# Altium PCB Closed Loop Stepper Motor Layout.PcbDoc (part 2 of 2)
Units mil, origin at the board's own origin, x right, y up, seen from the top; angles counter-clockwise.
Board outline 3560 x 2030 mil, 2 copper layers (Top Layer, Bottom Layer), stack 64.8 mil thick; 66 components, 54 nets, 285 pads, 203 vias.
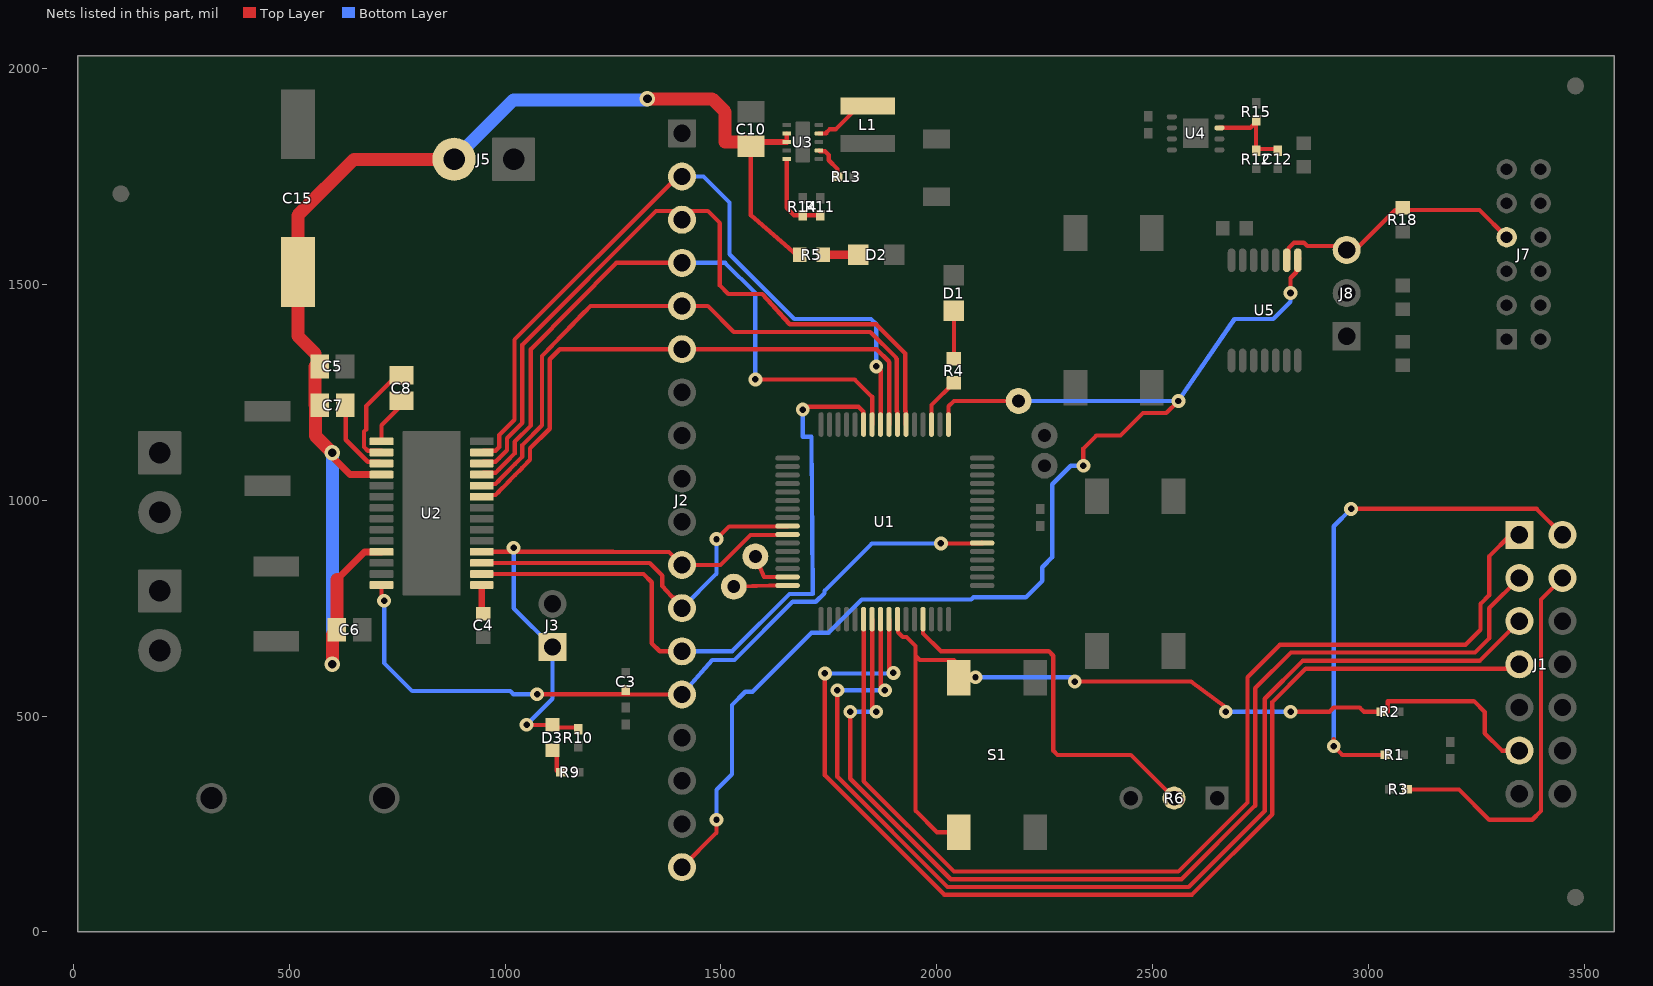
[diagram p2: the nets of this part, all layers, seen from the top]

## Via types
v1: diameter 32, hole 15, Top Layer to Bottom Layer, 165 vias
v2: diameter 19.68, hole 7.87, Top Layer to Bottom Layer, 16 vias
v3: diameter 19.68, hole 7.87, Top Layer to Bottom Layer, tented both sides, 12 vias
v4: diameter 36, hole 20, Top Layer to Bottom Layer, 4 vias
v5: diameter 32, hole 16, Top Layer to Bottom Layer, 3 vias
v6: diameter 32/32 (per signal layer), hole 16, Top Layer to Bottom Layer, 2 vias
v7: diameter 50, hole 28, Top Layer to Bottom Layer, 1 vias

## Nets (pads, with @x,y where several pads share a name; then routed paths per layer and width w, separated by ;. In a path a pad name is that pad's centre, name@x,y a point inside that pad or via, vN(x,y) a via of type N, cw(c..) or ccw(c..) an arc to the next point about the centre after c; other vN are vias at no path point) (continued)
I_ENCODER_3.3V: J2.18 pad.13 U1.17 U5.8 | length 2955.8
  Top Layer w10: J2.18@1410,150 1490,230 v1(1490,260) ; U1.17@2027.64,1175.39 2027.64,1217.64 2040,1230 pad.13@2190,1230 ; v1(2340,1080) 2340,1120 2370,1150 2425.9,1150 2477.95,1202.05 2532.05,1202.05 v1(2560,1230) ; v5(2820,1480) 2820,1515.71 2820.18,1515.71 2832.91,1528.44 2832.91,1552.28 U5.8@2840.63,1560
  Bottom Layer w10: v1(1490,260) 1490,329.37 1525.75,365.12 1525.75,525.75 1556.38,556.38 1573.33,556.38 1710.26,693.31 1749.7,693.31 1826.39,770 2080,770 2085.38,775.38 2206.77,775.38 2244.62,813.23 2244.62,845.01 2267.87,868.27 2267.87,1037.13 2310.75,1080 v1(2340,1080) ; pad.13@2190,1230 v1(2560,1230) 2690,1420 2780,1420 2820,1460 v5(2820,1480)
IENC_5V: J7.7 J8.3 R18.1 U5.9 | length 611.1
  Top Layer w10: U5.9@2815.04,1560 2815.04,1583.84 2827.77,1596.57 2850.8,1596.57 2858.5,1588.87 J8.3@2978.87,1588.87 ; J8.3@2970,1580 J8.3@2978.87,1588.87 ; J7.7@3320.63,1609.37 3257.64,1672.36 3080,1672.36 3062.36,1672.36 J8.3@2978.87,1588.87
M0: J2.4 U1.26 U2.25 | length 1537.8
  Top Layer w10: U2.25@946.14,1059.57 950,1063.43 977.89,1063.43 986.57,1072.11 986.57,1072.42 1004.45,1090.3 1004.45,1090.61 1022.32,1108.48 1022.32,1135.75 1060,1173.43 1060,1350 1257.87,1550 J2.4@1410,1550 ; v1(1580,1280) 1810,1280 1850.47,1239.53 U1.26@1850.47,1175.39
  Bottom Layer w10: J2.4@1410,1550 1510,1550 1580,1480 v1(1580,1280)
M1: J2.5 U1.23 U2.24 | length 1429.5
  Top Layer w10: U2.24@946.14,1033.98 950,1037.83 977.89,1037.83 986.57,1046.52 986.57,1046.83 1004.45,1064.7 1004.45,1065.02 1022.32,1082.89 1022.32,1083.2 1040.2,1101.08 1040.2,1128.03 1085.75,1173.58 1085.75,1334.34 1185,1436.76 1198.25,1450 J2.5@1390,1450 ; J2.5@1410,1450 1470,1450 1530,1390 1846.11,1390 1906.75,1329.36 1906.75,1328.53 1907.87,1327.4 1907.87,1206.56 1908.62,1205.81 1908.62,1176.3 U1.23@1909.53,1175.39
MSP_RST: J1.11 R2.1 S1.3 S1.4 U1.58 | length 2150.4
  Top Layer w10: U1.58@1909.53,724.61 1910.43,723.7 1910.43,694.19 1921.43,683.19 1930,683.19 1950.94,662.24 1950.94,640 ; S1.4@2051.42,230.87 2001.02,230.87 1950.94,280.94 1950.94,640 ; v1(2090,590) 2080,590 2040,630 1960.94,630 1950.94,640 ; v1(2320,580) 2590,580 2670,520 v1(2670,510) ; v1(2820,510) 2910,510 2920,520 2980,520 2990,510 3026.38,510 3045,510 3045,534.68 3244.68,534.68 3270,509.37 3270,460 3310,420 J1.11@3350,420
  Bottom Layer w10: v1(2090,590) 2310,590 v1(2320,580) ; v1(2670,510) v1(2820,510)
NetC8_1: C8.1 U2.2 | length 260.5
  Top Layer w10: U2.2@713.86,1110.75 713.86,1114.61 682.11,1114.61 673.43,1123.29 673.43,1159.14 678.35,1164.06 678.35,1218.35 C8.1@760,1300
NetC8_2: C8.2 U2.1 | length 105.3
  Top Layer w10: U2.1@716.34,1136.34 U2.1@713.86,1136.34 713.86,1173.86 C8.2@760,1220
NetC12_2: C12.2 R12.1 R15.2 U4.3 | length 203.3
  Top Layer w10: U4.3@2655.12,1862.8 2726.42,1862.8 2740,1876.38 2740,1813.62 C12.2@2790,1813.62
NetD1_1: D1.1 R4.1 | length 107.2
  Top Layer w10: R4.1@2040,1331.5 D1.1@2040,1438.66
NetD2_1: D2.1 R5.1 | length 77.2
  Top Layer w20: R5.1@1741.5,1568.7 D2.1@1818.66,1568.7
NetD3_1: D3.1 R9.1 | length 47.2
  Top Layer w10: R9.1@1120,373.31 D3.1@1120,420.47
NetJ1_2: J1.2 R1.1 | length 1222.5
  Top Layer w10: 2920,446.38 v1(2920,430) 2940,410 R1.1@3036.38,410 ; v1(2960,980) 3390,980 J1.2@3450,920
  Bottom Layer w10: v1(2920,430) 2920,940 v1(2960,980)
NetJ1_4: J1.4 R3.1 | length 904.4
  Top Layer w10: R3.1@3093.62,330 3210,330 3280,260 3380,260 3400,280 3400,770 J1.4@3450,820
NetL1_1: L1.1 U3.9 | length 120.1
  Top Layer w10: U3.9@1727.4,1849.69 1744.13,1849.69 1744.13,1851.71 1751.68,1859.25 1765.94,1859.25 L1.1@1820,1913.31
NetR11_1: R11.1 R14.1 U3.5 | length 197.7
  Top Layer w10: U3.5@1652.6,1790.63 1652.6,1677.4 1669.69,1660.31 R14.1@1690,1660.31 R11.1@1730,1660.31
NetR13_1: R13.1 U3.7 | length 85.2
  Top Layer w10: U3.7@1727.4,1810.32 1729.29,1808.43 1741.42,1808.43 1750.12,1799.73 1750.12,1787.6 1770.32,1767.4 R13.1@1770.32,1750
NFAULT: D3.2 J2.11 J3.1 R10.1 U1.42 U2.18 | length 1369.4
  Top Layer w10: U2.18@946.14,880.43 1250,880.43 1380,880 J2.11@1410,850 J2.11@1430,850 ; v1(1050,480) 1050.47,479.53 D3.2@1110,479.53 D3.2@1115.91,479.53 ; D3.2@1115.91,473.62 R10.1@1170,473.62 ; J2.11@1410,870 J2.11@1430,850 ; U1.42@1653.7,919.57 1568.93,919.57 1499.37,850 J2.11@1430,850
  Bottom Layer w10: v1(1020,890) 1020,750 J3.1@1110,660 1110,540 v1(1050,480)
NSLEEP: J2.12 U1.41 U2.17 | length 941.3
  Top Layer w10: U2.17@946.14,854.84 1335.16,854.84 1364.65,825.35 1364.65,801.21 J2.12@1410,750 ; J2.12@1391.21,774.65 1408.36,774.65 J2.12@1410,773.01 ; J2.12@1410,770 J2.12@1430,750 ; v1(1490,910) 1519.25,939.25 1653.7,939.25 U1.41@1654.61,940.16
  Bottom Layer w10: J2.12@1410,750 1490,830 v1(1490,910)
P1.6: pad.5 U1.47 | length 106.6
  Top Layer w10: pad.5@1580,870 1600,822.05 U1.47@1654.61,822.05
P1.7: pad.6 U1.48 | length 124.6
  Top Layer w10: pad.6@1530,800 1612.36,802.36 U1.48@1654.61,802.36
POT: R6.2 U1.61 | length 901.5
  Top Layer w10: U1.61@1968.58,724.61 1968.58,691.42 2010,650 2260,650 2270,640 2270,420 2280,410 2450,410 R6.2@2550,310
STATUS: R4.2 U1.19 | length 119.8
  Top Layer w10: U1.19@1989.17,1176.3 U1.19@1988.27,1175.39 1988.27,1220.71 R4.2@2040,1272.44
STEP: J2.6 U1.24 U2.23 | length 1367.7
  Top Layer w10: U2.23@946.14,1008.39 950,1012.24 977.89,1012.24 986.57,1020.93 986.57,1021.24 1004.45,1039.11 1004.45,1039.43 1022.32,1057.3 1022.32,1057.61 1040.2,1075.49 1040.2,1075.8 1058.07,1093.67 1058.07,1120.31 1103.62,1165.87 1103.62,1326.83 1126.8,1350 J2.6@1410,1350 ; J2.6@1400,1360 J2.6@1410,1350 ; U1.24@1889.84,1175.39 1890,1175.55 1890,1320 1888.87,1321.13 1888.87,1321.96 1860.83,1350 J2.6@1410,1350
TCK: J1.7 U1.57 | length 2620.8
  Top Layer w10: v1(1741.13,598.87) 1741.13,363.04 2017.79,86.38 2591.66,86.38 2777.87,272.6 2777.87,532.6 2855.28,610 3340,610 J1.7@3350,620 ; U1.57@1889.84,724.61 1889.84,610.16 v1(1900,600)
  Bottom Layer w10: v1(1741.13,598.87) 1898.87,598.87 v1(1900,600)
TDI: J1.3 U1.55 | length 2569.5
  Top Layer w10: v1(1800,510) 1800,354.72 2032.6,122.13 2567.4,122.13 2737.87,292.6 2737.87,564.39 2820.75,647.26 3247.26,647.26 3280,680 3280,750 J1.3@3350,820 ; U1.55@1850.47,724.61 1850.47,519.53 v1(1860,510)
  Bottom Layer w10: v1(1800,510) v1(1860,510)
TDO: J1.1 U1.54 | length 2562.1
  Top Layer w10: U1.54@1830.79,724.61 1830.79,349.21 2040,140 2560,140 2720,300 2720,590 2795.14,665.14 3225.14,665.14 3260,700 3260,760 3280,780 3280,870 3330,920 J1.1@3350,920
TMS: J1.5 U1.56 | length 2572.3
  Top Layer w10: v1(1770,560) 1770,359.44 2025.19,104.25 2584.25,104.25 2760,280 2760,540 2847.87,627.87 3257.87,627.87 J1.5@3350,720 ; U1.56@1870.16,724.61 1870.16,569.84 v1(1880,560)
  Bottom Layer w10: v1(1770,560) v1(1880,560)
TOFF: J2.13 U1.27 U2.16 | length 1646.5
  Top Layer w10: U2.16@946.14,829.25 1320.75,829.25 1340,810 1340,668.42 1358.42,650 J2.13@1410,650 ; J2.13@1400,660 1410,670 J2.13@1430,650 ; v1(1690,1210) 1696.81,1216.81 1818.88,1216.81 1829.88,1205.81 1829.88,1176.3 U1.27@1830.79,1175.39
  Bottom Layer w10: J2.13@1410,650 1526.22,650 1658.9,782.68 1712.68,782.68 1710,1146.85 1690,1146.85 v1(1690,1210)
TRQ0: J2.2 U1.25 U2.27 | length 1752.3
  Top Layer w10: U2.27@946.14,1110.75 950,1114.61 977.89,1114.61 986.57,1123.29 986.57,1151.18 1022.13,1186.73 1022.13,1372.13 1400,1750 J2.2@1410,1750 ; v1(1860,1310) 1870.16,1299.84 U1.25@1870.16,1175.39
  Bottom Layer w10: J2.2@1410,1750 1460,1750 1520,1690 1520,1570 1670,1420 1847.87,1420 1860,1407.87 v1(1860,1310)
TRQ1: J2.3 U1.22 U2.26 | length 1735
  Top Layer w10: U2.26@946.14,1085.16 950,1089.02 977.89,1089.02 986.57,1097.7 986.57,1098.01 1004.45,1115.89 1004.45,1143.78 1040,1179.33 1040,1360 1350,1670 1470,1670 1497.87,1642.13 1497.87,1497.4 1517.4,1477.87 1595.69,1477.87 1660,1407.87 1859.53,1407.87 1927.4,1340 1927.4,1206.72 1928.31,1205.81 1928.31,1175.39 U1.22@1929.21,1175.39
V3P3: C4.1 U2.15 | length 67.7
  Top Layer w10: C4.1@946.14,741.42 C4.1@950,737.56
  Top Layer w16: C4.1@946.14,741.42 U2.15@946.14,803.66
VCP: C7.1 U2.3 | length 176.1
  Top Layer w10: C7.1@631.12,1210.65 631.12,1140 682.11,1089.02 710,1089.02 U2.3@713.86,1085.16
VM: C5.1 C6.1 C7.2 C10.1 C15.1 J5.2 R5.2 U2.4 U2.11 U3.2 U3.3 | length 3151.1
  Top Layer w10: C7.2@560,1220.47 C7.2@560.47,1220 ; v4@600,1100 v4(600,1110) ; 1569.53,1660.47 C10.1@1569.53,1830 ; 1570,1660 R5.2@1675.55,1568.7 ; C10.1@1570,1830.47 C10.1@1570.47,1830 ; U3.3@1652.6,1830 U3.2@1652.6,1849.69
  Top Layer w13: C10.1@1570.47,1830 U3.3@1652.6,1830
  Top Layer w16: v4@600,1100 640.43,1059.57 U2.4@713.86,1059.57 ; 610.47,815.98 674.92,880.43 U2.11@713.86,880.43
  Top Layer w30: C7.2@560,1220.47 C5.1@560,1310 ; 560,1340.47 520,1380.47 C15.1@520,1528.74 520,1660 650,1790 J5.2@882,1790 ; C7.2@560.47,1220 560.47,1149.53 v4(600,1110) ; v4(600,620) C6.1@600,689.53 ; C6.1@610.47,700 610.47,815.98 ; v4(1330,1930) 1480,1930 1510,1900 1510,1830 C10.1@1569.53,1830
  Bottom Layer w30: v4(600,620) v4(600,1110) ; J5.2@882,1790 1019.8,1927.8 v4@1327.8,1927.8
VREF: C3.1 J2.14 U1.6 U2.14 | length 1759.3
  Top Layer w10: U2.14@713.86,803.66 713.86,779.42 720,773.28 v1(720,767.24) ; v1(1074.23,550.59) C3.1@1279.41,550.59 ; C3.1@1280,550 J2.14@1390,550 ; v1(2010,900) U1.6@2104.61,900 ; U1.6@2104.49,901.69 U1.6@2105.39,900.79 U1.6@2106.18,900
  Top Layer w16: J2.14@1390,550 J2.14@1410,570
  Bottom Layer w10: v1(720,767.24) 720,622.79 784.79,558 1011.96,558 1019.37,550.59 v1(1074.23,550.59) ; J2.14@1410,550 1480,630 1531.5,630 1666.3,764.8 1720.08,764.8 1740,784.72 1740,790.08 1849.92,900 v1(2010,900)
pads on no net: FID1.1 FID2.1 FID3.1 J1.6 J1.8 J1.10 J1.12 J1.13 J1.14 J7.5 J7.6 J7.8 J7.9 J7.10 J7.11 U1.2 U1.3 U1.4 U1.7 U1.8 U1.9 U1.16 U1.18 U1.20 U1.21 U1.28 U1.29 U1.30 U1.31 U1.32 U1.33 U1.34 U1.35 U1.39 U1.43 U1.44 U1.45 U1.46 U1.49 U1.50 U1.51 U1.52 U1.53 U1.59 U1.60 U2.29@830,970 U3.11@1690,1804.8 U3.11@1690,1855.2 U4.2 U4.6 U4.7 U5.11

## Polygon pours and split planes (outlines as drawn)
GND on Bottom Layer "Bottom Layer-GND" (solid, remove dead copper, pour order 1): 0,0 4950,0 4950,3450 0,3450
GND on Top Layer "Top Layer-GND" (solid, remove dead copper, pour order 0): -29.99,-24.59 4920.01,-24.59 4920.01,3425.41 -29.99,3425.41

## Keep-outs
Keep-Out Layer:
  text ".Layer_Name" at 577,-858.49 h60

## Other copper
Top Layer:
  rectangle net GND: 690,847 780,862
  region net 5V_BUCK: 3090,1590 3080,1600 3080,1580
  region net MSP_RST: 1950.94,628.96 1951.98,630 1970,630 1970,629.06 1950.94,610
  region net GND: 1988.27,760 1988.44,760.17 2007.95,760.17 2007.95,770.14 2012.05,774.24 1984.17,774.24
  region net 3.3V_LDO: 2160,672.36 2180,692.36 2180,690.93 2200,670.93
  text ".Layer_Name" at 577,-858.49 h60
Bottom Layer:
  text ".Layer_Name" at 577,-858.49 h60

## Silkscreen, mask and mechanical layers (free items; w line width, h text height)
Top Overlay:
  lines w10: 2320,310 ccw(c2440.21,189.79) 2360.21,39.79 2360.21,79.79 ; 2340,20 2359.79,39.79 ; 2729.79,315.1 cw(c2649.79,165.1) 2764.67,39.79 ; 2740,60 2759.79,40.21 ; 2759.79,39.79 2799.79,39.79
  text "GND" at 1228,1826 h50
  text "TRQ0" at 1470,1740 h50
  text "MSP STATUS" at 2100,1660 h72.83 r270
  text "VM   GND" at 840,1630 h30
  text "TRQ1" at 1220,1620 h50
  text "VM" at 1810,1620 h72.83
  text "M0" at 1470,1550 h50
  text "M1" at 1230,1430 h50
  text "STEP" at 1470,1350 h50
  text "DRV RESET" at 2270,1270 h72.83 r90
  text "DIR" at 1260,1240 h50
  text "ENABLE" at 1473.49,1143.72 h50
  text "AO1 AO2" at 340,1120 h25 r270
  text "ADECAY" at 1160,1040 h50
  text "DRV DIR" at 2590,960 h70 r270
  text "BDECAY" at 1160,930 h50
  text "nFAULT" at 1160,854.84 h50
  text "BO2 BO1" at 330,810 h25 r270
  text "nSLEEP" at 1470,730 h50
  text "TOFF" at 1230,650 h50
  text "VREF" at 1470,530 h50
  text "ATE" at 1240,430 h50
  text "SPEED" at 2450,430 h72.83
  text "'.PRJ_Number'.PCB_Rev-" at 50,420 h80
  text "B_E3.3" at 1480,330 h50
  text "MSP RST" at 2000,310 h72.83 r90
  text "A_E3.3" at 1200,230 h50
  text "GND" at 450,210 h40
  text "I_E3.3" at 1470,140 h50
  text "SLOW" at 2100,40 h72.83
  text "FAST" at 2840,40 h72.83
  text ".Layer_Name" at 577,-858.49 h60
Bottom Overlay:
  text ".Layer_Name" at 577,-858.49 h60
Top Paste:
  text ".Layer_Name" at 577,-858.49 h60
Bottom Paste:
  text ".Layer_Name" at 577,-858.49 h60
Top Solder:
  text ".Layer_Name" at 577,-858.49 h60
  text ".Layer_Name" at 577,-858.49 h60
Bottom Solder:
  text ".Layer_Name" at 577,-858.49 h60
Drill Guide:
  text ".Layer_Name" at 577,-858.49 h60
M1 Board Outline:
  the board outline again, w10
  text ".Layer_Name" at 577,-858.49 h60
M2 Board Dimensions:
  rectangle: 0,-275 125,-150
  rectangle: 125,-400 500,-275
  lines w7: 0,-275 1000,-275 ; 125,-400 125,-150 ; 250,-400 250,-150 ; 500,-400 500,-150 ; 750,-400 750,-150 ; 0,-400 1000,-400 1000,-150 0,-150 0,-400
  text ".Layer_Name" at 577,-858.49 h60
M3 3D STEP Top:
  text ".Layer_Name" at 577,-858.49 h60
M4 3D STEP Bottom:
  text ".Layer_Name" at 577,-858.49 h60
M5 Assembly Top:
  lines w10: -292,-930.17 6308,-930.17 ; -292,-726.83 6310,-726.83 ; -292,-523.5 -292,-1133.5 3713,-1133.5 6310,-1133.5 6310,-523.5 -291.5,-523.5 -291.5,-1133.5 1284,-1133.5 ; 2173,-1133.5 2173,-523.5 ; 3440,-726.83 3440,-523.5 ; 4280,-726.83 4280,-523.5 ; 4902,-1140 4902,-937.17
  text "COMPONENTS MARKED 'DNP' SHOULD NOT BE POPULATED." at 1153.5,-318.5 h60
  text "ASSEMBLY VARIANT:" at 1153,-434 h60
  text ".VariantName" at 2189,-434 h60
  text "PCB VIEWED FROM TOP SIDE" at -228.5,-655.67 h60
  text "BOARD #:" at 2248,-655.67 h60
  text ".PRJ_Number" at 2793.5,-655.67 h60
  text "REV:" at 3638,-655.67 h60
  text ".PCB_Rev" at 3929.5,-655.67 h60
  text "SVN REV:" at 4476,-655.67 h60
  text ".VersionControl_RevNumber" at 4982,-655.67 h60
  text "TID #:" at 2248,-859 h60
  text ".TID" at 2793.5,-859 h60
  text "PLOT NAME =" at -228.5,-1064.34 h60
  text ".plot_File_Name" at 577,-1064.34 h60
  text "GENERATED    :" at 2250,-1064.34 h60
  text ".Print_Date" at 3119.5,-1064.34 h60
  text ".Print_Time" at 3848.5,-1064.34 h60
  text "TEXAS INSTRUMENTS" at 5113,-1064.34 h60
M6 Assembly Bottom:
  lines w10: -292.5,-727.33 6309.5,-727.33 ; -290.5,-930.67 6309.5,-930.67 ; 1115.5,-1140.5 1115.5,-937.67 ; 1737.5,-727.33 1737.5,-524 ; 2577.5,-727.33 2577.5,-524 ; 3844.5,-1134 3844.5,-524 ; 4733.5,-1134 6309,-1134 6309,-524 -292.5,-524 -292.5,-1134 2304.5,-1134 6309.5,-1134 6309.5,-524
  text "COMPONENTS MARKED 'DNP' SHOULD NOT BE POPULATED." at 6102,-318 h60
  text ".VariantName" at 5058,-434 h60
  text "ASSEMBLY VARIANT:" at 6097,-434 h60
  text ".VersionControl_RevNumber" at 1035.5,-656.17 h60
  text "SVN REV:" at 1541.5,-656.17 h60
  text ".PCB_Rev" at 2088,-656.17 h60
  text "REV:" at 2379.5,-656.17 h60
  text ".PRJ_Number" at 3224,-656.17 h60
  text "BOARD #:" at 3769.5,-656.17 h60
  text "PCB VIEWED FROM BOTTOM SIDE" at 6246,-656.17 h60
  text ".TID" at 3224,-859.5 h60
  text "TID #:" at 3769.5,-859.5 h60
  text "TEXAS INSTRUMENTS" at 904.5,-1064.84 h60
  text ".Print_Time" at 2169,-1064.84 h60
  text ".Print_Date" at 2898,-1064.84 h60
  text "GENERATED    :" at 3767.5,-1064.84 h60
  text ".plot_File_Name" at 5440.5,-1064.84 h60
  text "PLOT NAME =" at 6246,-1064.84 h60
M9 Title Sheet:
  drawing of 57 lines, arcs and shapes, not listed
  text "1" at 739.84,8036.5 h70
  text "2" at 3235.5,8036.5 h70
  text "3" at 5724.84,8036.5 h70
  text "4" at 8231.51,8036.5 h70
  text "5" at 10730.5,8036.5 h70
  text "6" at 13235.5,8036.5 h70
  text "A" at -416.5,6893.5 h70
  text "A" at 14383.5,6893.5 h70
  text "B" at -416.5,4513.5 h70
  text "B" at 14383.5,4513.5 h70
  text "C" at -416.5,2138.5 h70
  text "C" at 14383.5,2138.5 h70
  text "PROJECT TITLE:" at 11343.5,277.5 h45
  text ".PRJ_Title" at 11393.5,144.17 h70
  text "DESIGNED FOR:" at 11343.5,-23.5 h45
  text ".PRJ_Customer" at 11393.5,-163.5 h70
  text "D" at -416.5,-231.5 h70
  text "D" at 14383.5,-231.5 h70
  text "FILE NAME:" at 11343.5,-323.5 h45
  text ".PCB_File_Name_No_Path" at 11393.5,-443.5 h70
  text "Texas Instruments (TI) and/or its licensors do not warrant the accuracy or completeness of this specification" at 6374,-605.34 h45
  text "ENGINEER:" at 11343.5,-613.5 h45
  text "LAYOUT BY:" at 12848.5,-613.5 h45
  text "or any information contained therein. TI and/or its licensors do not warrant that this design will meet" at 6329.01,-718 h45
  text ".PRJ_Engineer" at 11393.5,-768.49 h70
  text ".PCB_Layout" at 12899,-768.49 h70
  text "the specifications, will be suitable for your application or fit for any particular purpose, or will operate in" at 6329.01,-830.67 h45
  text ".Layer_Name" at 577,-858.49 h60
  text "ALTIUM DESIGNER VERSION:" at 12848.5,-923.5 h45
  text "an implementation. TI and/or its licensors do not warrant that the design is production worthy. You should" at 6329.01,-943.33 h45
  text "completely validate and test your design implementation to confirm the system functionality for your application." at 6374,-1056 h45
  text ".print_Scale" at 11393.5,-1056.83 h70
  text ".Application_BuildNumber" at 12899,-1056.83 h70
  text "1" at 739.84,-1263.5 h70
  text "2" at 3235.5,-1263.5 h70
  text "3" at 5724.84,-1263.5 h70
  text "4" at 8231.51,-1263.5 h70
  text "5" at 10730.5,-1263.5 h70
  text "6" at 13235.5,-1263.5 h70
M10 Fab Notes:
  drawing of 173 lines, arcs and shapes, not listed
  text "DESIGN INFORMATION" at 12378.02,6201 h60
  text "MIN. TRACK WIDTH:" at 11733.46,6021 h60
  text "8" at 12829.7,6021 h60
  text "MIL" at 12984.46,6021 h60
  text "MIN. CLEARANCE:" at 11733.46,5889 h60
  text "0.2" at 12769.7,5889 h60
  text "mm" at 12984.46,5889 h60
  text "MIN. VIA PAD SIZE:" at 11733.46,5757 h60
  text "24" at 12799.71,5757 h60
  text "MIL" at 12984.46,5757 h60
  text "0.05mm (2MIL)" at 12428.46,5615.29 h60
  text "MINIMUM ANNULAR RING" at 11404.23,5611 h60
  text "EXTERNAL" at 13136.46,5611 h60
  text "PER" at 11604.23,5493 h60
  text "IPC-D-275 CLASS 2 LEVEL C" at 11824.23,5493 h60
  text "MIL, HOLES" at 13312.46,5380.71 h60
  text "+/-" at 12920,5380 h60
  text "+/-" at 13774,5380 h60
  text "REGISTRATION TOLERANCES:" at 11404.23,5375 h60
  text "METAL" at 12604,5375 h60
  text "5" at 13180.2,5375 h60
  text "3" at 14013.2,5375 h60
  text "MIL" at 14129.46,5375 h60
  text "+/-" at 13774,5262 h60
  text "HOLE SIZE TOLERANCE (UNLESS OTHERWISE SPECIFIED):" at 11404.23,5257 h60
  text "3" at 14013.2,5257 h60
  text "MIL" at 14129.46,5257 h60
  text "MATERIAL:" at 11329.46,5047.54 h60
  text "FR-4 High Tg" at 12315.9,4907.21 h60
  text "FR-408" at 11750.46,4898.64 h60
  text "OTHER" at 13238.46,4898.64 h60
  text "X" at 12161,4895 h60
  text "62 MIL (1.6mm) +/-10%" at 12070.56,4735.92 h60
  text "THICKNESS:" at 11404.23,4731.64 h60
  text "X" at 11942.4,4731.64 h60
  text "OTHER" at 13355.46,4731.64 h60
  text "TOLERANCE:" at 11404.23,4573.64 h60
  text "X" at 12243.53,4573.64 h60
  text "ANSI IPC-6012 TYPE 3 CLASS 2" at 12430.48,4573.64 h60
  text "OTHER +/-" at 12430.46,4417.64 h60
  text "BOW & TWIST:" at 11404.23,4260.64 h60
  text "X" at 12243.53,4260.64 h60
  text "ANSI IPC-6012 TYPE 3 CLASS 2" at 12430.48,4260.64 h60
  text "OTHER +/-" at 12430.46,4102.13 h60
  text "DRILLING:" at 11329.46,3963.64 h60
  text "REFERENCE:" at 11404.23,3846.64 h60
  text "X" at 12052.46,3846.64 h60
  text "AS SHOWN" at 12239.46,3846.64 h60
  text "X" at 12953.46,3846.64 h60
  text "NC_DRILL FILES" at 13090.46,3846.64 h60
  text "PTH COPPER THICKNESS:" at 11404.23,3688.64 h60
  text "X" at 12534.46,3688.64 h60
  text "20-30 um" at 12671.46,3688.64 h60
  text "OTHER" at 13388.46,3688.64 h60
  text "BOARD FINISH:" at 11329.46,3529.64 h60
  text "SILKSCREEN:" at 11484.68,3411.64 h60
  text "X" at 12433.46,3411.64 h60
  text "TOP" at 12559.46,3411.64 h60
  text "X" at 12943.46,3411.64 h60
  text "BOTTOM" at 13070.46,3411.64 h60
  text "SILKSCREEN COLOR:" at 11484.68,3244.64 h60
  text "X" at 12432.42,3244.64 h60
  text "WHITE" at 12559.46,3244.64 h60
  text "OTHER" at 13070.46,3244.64 h60
  text "X" at 12563.42,3085.44 h60
  text "GREEN" at 12690.46,3085.44 h60
  text "OTHER" at 13308.46,3085.44 h60
  text "SOLDER RESIST COLOR:" at 11484.68,3074.64 h60
  text "X" at 12563.42,2915.44 h60
  text "MATTE" at 12690.46,2915.44 h60
  text "SEMI-GLOSS" at 13308,2914.8 h60
  text "IMMERSION GOLD (ENIG)" at 12390.46,2726.92 h60
  text "ENEPIG" at 13728,2723.64 h60
  text "SURFACE FINISH:" at 11329.46,2722.64 h60
  text "X" at 12203.51,2722.64 h60
  text "IMM. TIN/SILVER OR EQUIV" at 11659,2565.64 h60
  text "OTHER" at 13090.46,2565.64 h60
  text "ARRAY/PANEL:" at 11329.46,2386.64 h60
  text "CUT AND TRIM PER M1 BOARD OUTLINE" at 12390.46,2382.35 h60
  text "N.C. ROUTE" at 12390.46,2230.64 h60
  text "X" at 13069.46,2230.64 h60
  text "V. SCORE" at 13256.46,2230.64 h60
  text "CERTIFICATION:" at 11329.46,2093.64 h60
  text "MATERIALS AND WORKMANSHIP FOR ALL PCBS" at 12054.46,2093.64 h60
  text "TO MEET OR EXCEED THE REQUIREMENTS OF:" at 12054.46,1995.64 h60
  text "X" at 11680.96,1859.13 h60
  text "ANSI IPC-A-600F CLASS ->" at 11819.96,1859.13 h60
  text "X" at 13459.02,1859.13 h60
  text "2" at 13577.96,1859.14 h60
  text "1" at 13262.96,1857.64 h60
  text "3" at 13931.96,1857.64 h60
  text "X" at 12495.02,1699.64 h60
  text "RoHS" at 12631.96,1699.64 h60
  text "OTHER" at 13276.36,1699.64 h60
  text "PER ORDER" at 13673.42,1699.64 h60
  text "ALL BOARDS MUST MEET OR EXCEED UL94-V0 REQUIREMENTS." at 11357,1534 h60
  text "PCB MUST BEAR THE UL94V-0 UL REGISTERED MATERIAL ID NUMBER" at 11357,1414 h60
  text "ADDITIONAL REQUIREMENTS:" at 11329.46,1240.64 h60
  text "MICROSECTION:" at 11404.23,1125.64 h60
  text "YES" at 12309.96,1125.64 h60
  text "REQUIRED" at 13171.46,969.49 h60
  text "BARE BOARD ELEC. TEST:" at 11404.23,966.64 h60
  text "NONE" at 12709.96,966.64 h60
  text "X" at 13044.46,966.64 h60
  text "PER ORDER" at 13763.46,966.64 h60
  text ".Layer_Name" at 577,-858.49 h60
M11 Gerber Information:
  lines w10: -292,-930.17 6308,-930.17 ; -292,-726.83 6310,-726.83 ; -292,-523.5 -292,-1133.5 3713,-1133.5 6310,-1133.5 6310,-523.5 -291.5,-523.5 -291.5,-1133.5 1284,-1133.5 ; 2173,-1133.5 2173,-523.5 ; 3440,-726.83 3440,-523.5 ; 4280,-726.83 4280,-523.5 ; 4902,-1140 4902,-937.17
  text "ALL ARTWORK VIEWED FROM TOP SIDE" at -228.5,-655.67 h60
  text "BOARD #:" at 2248,-655.67 h60
  text ".PRJ_Number" at 2793.5,-655.67 h60
  text "REV:" at 3638,-655.67 h60
  text ".PCB_Rev" at 3929.5,-655.67 h60
  text "SVN REV:" at 4476,-655.67 h60
  text ".VersionControl_RevNumber" at 4982,-655.67 h60
  text "LAYER NAME =" at -228.5,-858.49 h60
  text "TID #:" at 2248,-859 h60
  text ".TID" at 2793.5,-859 h60
  text "PLOT NAME =" at -228.5,-1064.34 h60
  text ".plot_File_Name" at 577,-1064.34 h60
  text "GENERATED    :" at 2250,-1064.34 h60
  text ".Print_Date" at 3119.5,-1064.34 h60
  text ".Print_Time" at 3848.5,-1064.34 h60
  text "TEXAS INSTRUMENTS" at 5113,-1064.34 h60
M12 Stackup:
  drawing of 191 lines, arcs and shapes, not listed
  text "Layer" at 9797.84,7830 h60
  text "Name" at 10207.76,7830 h60
  text "Material" at 11137.5,7830 h60
  text "Thickness" at 11997.27,7830 h60
  text "Constant" at 12647.1,7830 h60
  text "Board Layer Stack" at 13216.96,7830 h60
  text "1" at 9797.84,7710 h60
  text "Top Overlay" at 10207.76,7710 h60
  text "2" at 9797.84,7590 h60
  text "Top Solder" at 10207.76,7590 h60
  text "Solder Resist" at 11137.5,7590 h60
  text "0.40mil" at 11997.27,7590 h60
  text "3.5" at 12647.1,7590 h60
  text "3" at 9797.84,7470 h60
  text "Top Layer" at 10207.76,7470 h60
  text "Copper" at 11137.5,7470 h60
  text "2.80mil" at 11997.27,7470 h60
  text "4" at 9797.84,7350 h60
  text "Dielectric1" at 10207.76,7350 h60
  text "FR-4" at 11137.5,7350 h60
  text "59.20mil" at 11997.27,7350 h60
  text "4.8" at 12647.1,7350 h60
  text "5" at 9797.84,7230 h60
  text "Bottom Layer" at 10207.76,7230 h60
  text "Copper" at 11137.5,7230 h60
  text "2.80mil" at 11997.27,7230 h60
  text "6" at 9797.84,7110 h60
  text "Bottom Solder" at 10207.76,7110 h60
  text "Solder Resist" at 11137.5,7110 h60
  text "0.40mil" at 11997.27,7110 h60
  text "3.5" at 12647.1,7110 h60
  text "7" at 9797.84,6990 h60
  text "Bottom Overlay" at 10207.76,6990 h60
  text ".Layer_Name" at 577,-858.49 h60
M13 Component Bodies Top:
  text ".Layer_Name" at 577,-858.49 h60
M14 Component Bodies Bottom:
  text ".Layer_Name" at 577,-858.49 h60
M15 Courtyards Top:
  text ".Layer_Name" at 577,-858.49 h60
M16 Courtyards Bottom:
  text ".Layer_Name" at 577,-858.49 h60
Drill Drawing:
  circle w10: c4483.82,1691.52 r16.6
  circle w10: c4483.82,1691.52 r27.67
  circle w10: c4483.82,1193.52 r27.67
  lines w10: 4456.16,557.18 4469.99,557.18 4483.82,543.35 4497.66,557.18 4511.49,557.18 4497.66,571.02 4511.49,584.85 4497.66,584.85 4483.82,598.68 4469.99,584.85 4456.16,584.85 4469.99,571.02 4456.16,557.18 ; 4456.16,667.85 4483.82,681.68 4511.49,667.85 4497.66,695.52 4511.49,723.18 4483.82,709.35 4456.16,723.18 4469.99,695.52 4456.16,667.85 ; 4456.16,792.35 4511.49,792.35 4511.49,847.68 4456.16,847.68 4456.16,792.35 ; 4456.16,972.18 4511.49,972.18 4483.82,916.85 4456.16,972.18 ; 4456.16,1069.02 4483.82,1041.35 4511.49,1069.02 4483.82,1096.68 4456.16,1069.02 ; 4456.16,1304.18 4469.99,1304.18 4469.99,1290.35 4497.66,1290.35 4497.66,1304.18 4511.49,1304.18 4511.49,1331.85 4497.66,1331.85 4497.66,1345.68 4469.99,1345.68 4469.99,1331.85 4456.16,1331.85 4456.16,1304.18 ; 4456.16,1428.68 4469.99,1428.68 4483.82,1414.85 4497.66,1428.68 4511.49,1428.68 4497.66,1442.52 4511.49,1456.35 4497.66,1456.35 4483.82,1470.18 4469.99,1456.35 4456.16,1456.35 4469.99,1442.52 4456.16,1428.68 ; 4456.16,1594.68 4511.49,1594.68 4483.82,1539.35 4456.16,1594.68 ; 4456.16,1788.35 4456.16,1802.18 4469.99,1816.02 4456.16,1829.85 4456.16,1843.68 4469.99,1843.68 4483.82,1829.85 4497.66,1843.68 4511.49,1843.68 4511.49,1829.85 4497.66,1816.02 4511.49,1802.18 4511.49,1788.35 4497.66,1788.35 4483.82,1802.18 4469.99,1788.35 4456.16,1788.35 ; 4467.23,1434.22 4475.52,1434.22 4483.82,1425.92 4492.12,1434.22 4500.43,1434.22 4492.12,1442.52 4500.43,1450.82 4492.12,1450.82 4483.82,1459.12 4475.52,1450.82 4467.23,1450.82 4475.52,1442.52 4467.23,1434.22 ; 4467.23,1583.62 4500.43,1583.62 4483.82,1550.42 4467.23,1583.62
  lines w12: 4406,506 7638.19,506 ; 4406,1875.5 7638.19,1875.5 ; 4744.01,381.5 4744.01,2000 ; 5076.17,381.5 5076.17,2000 ; 5712.65,381.5 5712.65,2000 ; 5971.85,381.5 5971.85,2000 ; 6347.09,381.5 6347.09,2000 ; 7071.64,381.5 7071.64,2000 ; 4406,381.5 7638.19,381.5 7638.19,2000 4406,2000 4406,381.5
  text "Symbol" at 4480.7,1912.85 h72
  text "Quantity" at 4781.36,1912.85 h72
  text "Finished Hole Size" at 5113.52,1912.85 h72
  text "Plated" at 5750,1912.85 h72
  text "Hole Type" at 6009.2,1912.85 h72
  text "Drill Layer Pair" at 6384.44,1912.85 h72
  text "Hole Tolerance" at 7108.99,1912.85 h72
  text "28" at 4781.36,1788.35 h60
  text "7.87mil (0.200mm)" at 5113.52,1788.35 h60
  text "PTH" at 5750,1788.35 h60
  text "Round" at 6009.2,1788.35 h60
  text "Top Layer - Bottom Layer" at 6384.44,1788.35 h60
  text "165" at 4781.36,1663.85 h60
  text "15.00mil (0.381mm)" at 5113.52,1663.85 h60
  text "PTH" at 5750,1663.85 h60
  text "Round" at 6009.2,1663.85 h60
  text "Top Layer - Bottom Layer" at 6384.44,1663.85 h60
  text "5" at 4781.36,1539.35 h60
  text "16.00mil (0.406mm)" at 5113.52,1539.35 h60
  text "PTH" at 5750,1539.35 h60
  text "Round" at 6009.2,1539.35 h60
  text "Top Layer - Bottom Layer" at 6384.44,1539.35 h60
  text "4" at 4781.36,1414.85 h60
  text "20.00mil (0.508mm)" at 5113.52,1414.85 h60
  text "PTH" at 5750,1414.85 h60
  text "Round" at 6009.2,1414.85 h60
  text "Top Layer - Bottom Layer" at 6384.44,1414.85 h60
  text "12" at 4781.36,1290.35 h60
  text "27.56mil (0.700mm)" at 5113.52,1290.35 h60
  text "PTH" at 5750,1290.35 h60
  text "Round" at 6009.2,1290.35 h60
  text "Top Layer - Bottom Layer" at 6384.44,1290.35 h60
  text "+3.94mil/-0.00mil" at 7108.99,1290.35 h60
  text "1" at 4781.36,1165.85 h60
  text "28.00mil (0.711mm)" at 5113.52,1165.85 h60
  text "PTH" at 5750,1165.85 h60
  text "Round" at 6009.2,1165.85 h60
  text "Top Layer - Bottom Layer" at 6384.44,1165.85 h60
  text "5" at 4781.36,1041.35 h60
  text "30.00mil (0.762mm)" at 5113.52,1041.35 h60
  text "PTH" at 5750,1041.35 h60
  text "Round" at 6009.2,1041.35 h60
  text "Top Layer - Bottom Layer" at 6384.44,1041.35 h60
  text "3" at 4781.36,916.85 h60
  text "33.46mil (0.850mm)" at 5113.52,916.85 h60
  text "PTH" at 5750,916.85 h60
  text "Round" at 6009.2,916.85 h60
  text "Top Layer - Bottom Layer" at 6384.44,916.85 h60
  text "37" at 4781.36,792.35 h60
  text "40.00mil (1.016mm)" at 5113.52,792.35 h60
  text "PTH" at 5750,792.35 h60
  text "Round" at 6009.2,792.35 h60
  text "Top Layer - Bottom Layer" at 6384.44,792.35 h60
  text "6" at 4781.36,667.85 h60
  text "50.00mil (1.270mm)" at 5113.52,667.85 h60
  text "PTH" at 5750,667.85 h60
  text "Round" at 6009.2,667.85 h60
  text "Top Layer - Bottom Layer" at 6384.44,667.85 h60
  text "2" at 4781.36,543.35 h60
  text "51.18mil (1.300mm)" at 5113.52,543.35 h60
  text "PTH" at 5750,543.35 h60
  text "Round" at 6009.2,543.35 h60
  text "Top Layer - Bottom Layer" at 6384.44,543.35 h60
  text "268 Total" at 4781.36,418.85 h60
  text ".Layer_Name" at 577,-858.49 h60
M17 Embedded Cavity:
  text ".Layer_Name" at 577,-858.49 h60
M18 Embedded Assembly:
  text ".Layer_Name" at 577,-858.49 h60
M19 Embedded Keepout:
  text ".Layer_Name" at 577,-858.49 h60

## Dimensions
0,-400 to 1000,-400 on M2 Board Dimensions
0,0 to 10,2030 on M2 Board Dimensions
3570,0 to 10,2030 on M2 Board Dimensions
